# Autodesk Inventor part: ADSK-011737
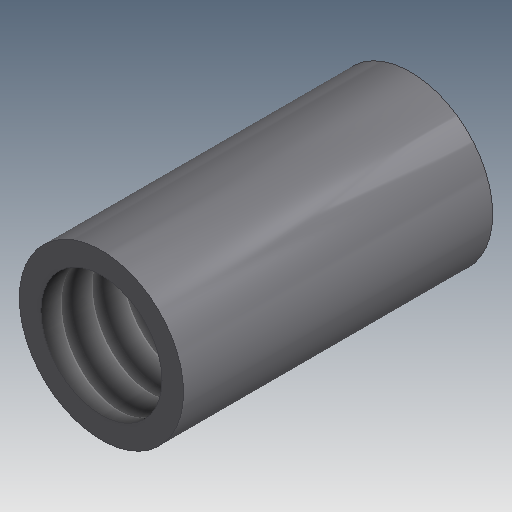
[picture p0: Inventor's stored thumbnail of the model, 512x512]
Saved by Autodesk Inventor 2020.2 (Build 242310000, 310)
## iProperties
Created: 1999-11
Part Number: ADSK-011737
Material: Acier doux
Description: HELICOIL,0.250-20NCX05.00
Document SubType Name: Modeling
Designer: lnowak
Density: 7.86 g/cm^3
Appearance: Metal-Steel(Polish)
Mass: 1.62502 g
Surface Area: 5.00351 cm^2
Volume: 0.206746 cm^3
Control State: 0
Checked Out: False
Last Check In By: lnowak
Master: False
Shininess: 0.0
Length Units: 11272
Angle Units: 11279
Time Units: 11290
Mass Units: 11286
Length Display Precision: 3
Angle Display Precision: 2
Compacted: True
Material Desc: HELICOIL,0.250-20NCX0.500
Material_Number: A094256
Dimensions: 0,3x0,5x0,3 in
Mass: 0,004 lb
VLT_Material: Acier doux
Density: 0.0
Volumn: 0.0
Area: 0.0
PropertySet Name: Model Information
Author: lnowak
Revision Number: -
Title: HELICOIL,0.250-20NCX05.00
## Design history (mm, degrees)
node "Extrusion1" dims "d1" = 12.7, "d2" = 0
node "Hole1" dims "d3" = 4.9784, "d4" = 9.525, "d5" = 6.35, "d6" = 60 deg, "d7" = 19.05, "d8" = 118 deg
node "Solide1"
node "Corps solides"
node "Corps surfaciques"
sketch "Sketch1"
  geometry: C1 r 3.373 at (0, 0)
  constraints: 1 centre point
  dimensions: "d0" = 6.74624 diameter of C1
sketch "Sketch2"
  geometry: C1 r 3.373 at (0, 0) reference; 1 further point
  constraints: 1 coincident
